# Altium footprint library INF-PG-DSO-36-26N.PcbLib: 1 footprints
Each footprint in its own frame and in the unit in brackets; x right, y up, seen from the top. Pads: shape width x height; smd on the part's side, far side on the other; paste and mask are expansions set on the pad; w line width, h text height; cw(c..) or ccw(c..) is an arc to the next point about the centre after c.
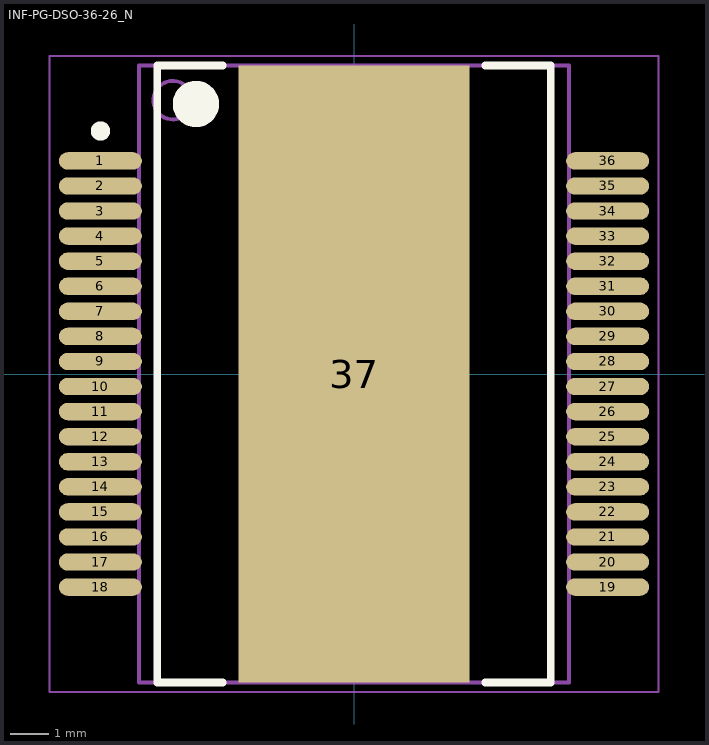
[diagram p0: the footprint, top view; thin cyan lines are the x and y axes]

## INF-PG-DSO-36-26_N [mm] "SOP, 36-Leads, Body 15.9x11mm, Pitch 0.65mm, Thermal Pad 16x6mm, IPC Medium Density"
height 3.5
pads (37):
  oval 2.15x0.45 smd: 1(-6.575,5.525) 2(-6.575,4.875) 3(-6.575,4.225) 4(-6.575,3.575) 5(-6.575,2.925) 6(-6.575,2.275) 7(-6.575,1.625) 8(-6.575,0.975) 9(-6.575,0.325) 10(-6.575,-0.325) 11(-6.575,-0.975) 12(-6.575,-1.625) 13(-6.575,-2.275) 14(-6.575,-2.925) 15(-6.575,-3.575) 16(-6.575,-4.225) 17(-6.575,-4.875) 18(-6.575,-5.525) 19(6.575,-5.525) 20(6.575,-4.875) 21(6.575,-4.225) 22(6.575,-3.575) 23(6.575,-2.925) 24(6.575,-2.275) 25(6.575,-1.625) 26(6.575,-0.975) 27(6.575,-0.325) 28(6.575,0.325) 29(6.575,0.975) 30(6.575,1.625) 31(6.575,2.275) 32(6.575,2.925) 33(6.575,3.575) 34(6.575,4.225) 35(6.575,4.875) 36(6.575,5.525)
  rect 6x16 smd: 37(0,0)
Top Overlay:
  circle w0.25: c-6.575,6.3 r0.125
  circle w0.6: c-4.1,7 r0.3
  lines w0.2: -3.4,-8 -5.1,-8 -5.1,8 -3.4,8 ; 3.4,-8 5.1,-8 5.1,8 3.4,8
Mechanical 13:
  circle w0.1: c-4.7,7.1 r0.5
  lines w0.1: -5.575,-8 -5.575,8 5.575,8 5.575,-8 -5.575,-8
Mechanical 15:
  lines w0.05: -7.9,-8.25 -7.9,8.25 7.9,8.25 7.9,-8.25 -7.9,-8.25
  lines w0.1: -0.5,0 0.5,0 ; 0,-0.5 0,0.5
3D body: height 3.5, standoff 0, extent -5.575,-8 5.575,8
3D body: height 3.5, standoff 0, extent -5.575,-8 5.575,8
